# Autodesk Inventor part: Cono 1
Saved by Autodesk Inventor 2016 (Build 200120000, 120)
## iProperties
Created: 2017-06
Part Number: Cono 1
Material: Generic
Document SubType Name: Modeling
Designer: Administrator
Appearance: Generic
Author: Administrator
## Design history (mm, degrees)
feature "Body1"
body "Solid1"
